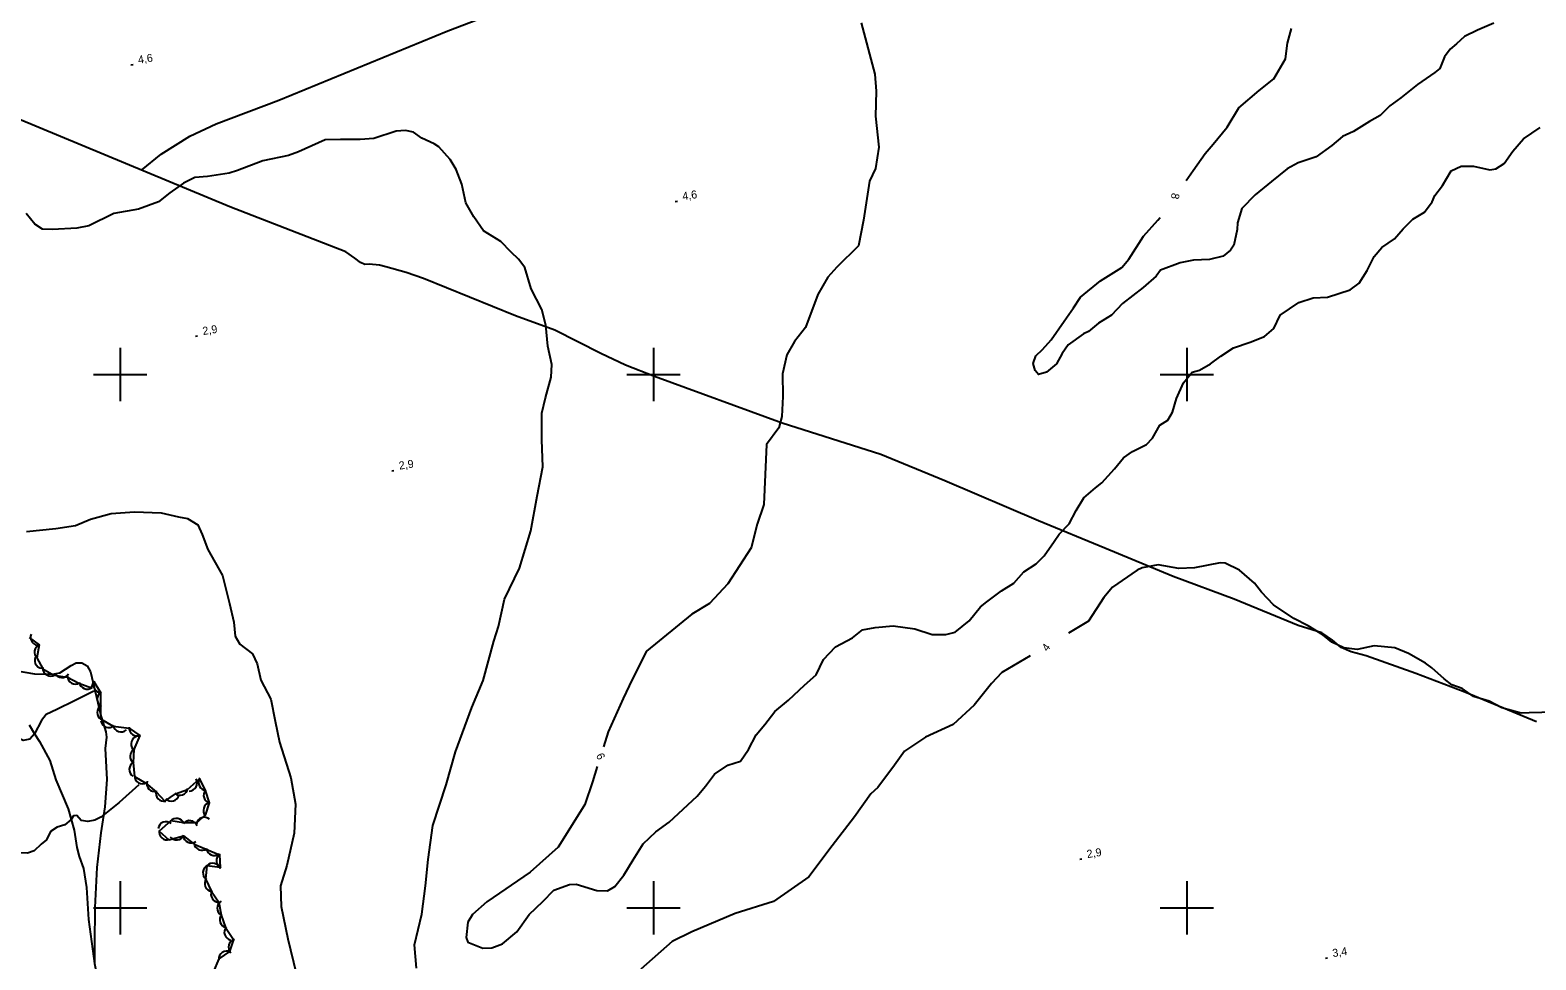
# Model space of a CAD drawing. Extents: x 643342 to 646936, y 5873857 to 5876103.
# Drawn here: x 644566 to 645131, y 5874980 to 5875329 of the extents above; entities that cross this region are included whole.
import ezdxf

# ---------------------------------------------------------------- set-up
doc = ezdxf.new("R2010")
doc.units = 0
for name, color, linetype in [('Niveau 2', 7, 'Continuous'), ('Niveau 22', 7, 'Continuous'), ('Niveau 3', 7, 'Continuous'), ('Niveau 4', 7, 'Continuous'), ('Niveau 44', 7, 'Continuous'), ('Niveau 61', 7, 'Continuous')]:
    doc.layers.add(name, color=color, linetype=linetype)

msp = doc.modelspace()

# ---------------------------------------------------------------- linework, layer by layer
at = {"layer": 'Niveau 2'}
for points in [[(644877.82, 5875331.83), (644882.97, 5875312.58), (644883.46, 5875306.17), (644883.2, 5875296.74), (644884.42, 5875285.11), (644883.2, 5875277.12), (644880.91, 5875272.44), (644878.75, 5875257.84), (644876.88, 5875248.14), (644868.67, 5875240.18), (644865.31, 5875236.39), (644861.62, 5875229.87), (644856.91, 5875217.54), (644852.86, 5875212.33), (644849.95, 5875207.34), (644848.3, 5875200.24), (644848.53, 5875191.67), (644848.07, 5875184.22), (644846.96, 5875179.99), (644842.31, 5875173.66), (644841.3, 5875151.19), (644838.84, 5875143.89), (644836.54, 5875134.95), (644827.79, 5875121.51), (644820.97, 5875114.07), (644814.35, 5875110.07), (644797.34, 5875096.17), (644791.92, 5875085.62), (644788.62, 5875078.46), (644783.03, 5875066), (644781.23, 5875060.3)], [(645115.06, 5875331.59), (645108.98, 5875328.98), (645104.09, 5875326.65), (645100.99, 5875323.96), (645098.66, 5875321.87), (645096.51, 5875319.03), (645094.79, 5875314.65), (645092.88, 5875313.12), (645086.48, 5875308.72), (645080.13, 5875303.67), (645076, 5875300.71), (645072.46, 5875297.04), (645068.44, 5875294.73), (645062.38, 5875291), (645058.33, 5875289.16), (645054.35, 5875285.74), (645048.45, 5875281.55), (645041.73, 5875279.23), (645037.53, 5875277.03), (645031.73, 5875272.32), (645025.54, 5875267.34), (645020.54, 5875262.12), (645018.9, 5875256.85), (645018.77, 5875254.31), (645017.58, 5875248.43), (645016.29, 5875246.49), (645013.6, 5875244.36), (645008.43, 5875243.06)], [(644999.69, 5875272.64), (645002.26, 5875276.43), (645006.81, 5875282.73), (645009.79, 5875286.24), (645015.09, 5875292.67), (645019.38, 5875299.88), (645027.07, 5875306.46), (645032.56, 5875310.73), (645036.88, 5875318.23), (645037.71, 5875324.13), (645039.22, 5875329.67)], [(644731.83, 5875075.08), (644736.15, 5875085.19), (644740.14, 5875099.99), (644741.84, 5875105.47), (644744.15, 5875115.74), (644749.73, 5875127.38), (644754.02, 5875141.37), (644756.31, 5875154.34), (644758.43, 5875165.29), (644758.17, 5875175.47), (644758.17, 5875185.44), (644759.43, 5875191.22), (644761.62, 5875198.98), (644761.88, 5875203.67), (644760.41, 5875210.55), (644759.67, 5875218.44), (644758.11, 5875224.37), (644754.12, 5875232), (644751.78, 5875240.04), (644749.38, 5875243.17), (644746.62, 5875245.74), (644742.78, 5875249.86), (644736.22, 5875253.77), (644732.56, 5875259.09), (644729.66, 5875264.35), (644728.12, 5875271.34), (644725.97, 5875276.8), (644723.75, 5875280.48), (644719.44, 5875285.32), (644717.75, 5875286.46), (644713.11, 5875288.5), (644709.96, 5875290.85), (644706.98, 5875291.46), (644703.5, 5875291.13), (644695.15, 5875288.45), (644690.03, 5875288.09), (644682.61, 5875288.03), (644676.93, 5875287.97), (644666.82, 5875283.36), (644663.08, 5875282.06), (644653.49, 5875279.98), (644643.99, 5875276.36), (644640.86, 5875275.36), (644632.71, 5875274.12), (644628.05, 5875273.85), (644623.79, 5875271.68), (644618.63, 5875268), (644614.37, 5875264.65), (644606.94, 5875261.88), (644597.65, 5875260.29), (644588.28, 5875255.68), (644583.72, 5875254.78), (644574.61, 5875254.27), (644570.96, 5875254.4), (644568.03, 5875256.25), (644564.83, 5875260.26)], [(645091.95, 5875264.62), (645092.91, 5875267), (645095.75, 5875270.74), (645099.01, 5875276.33), (645102.78, 5875278.09), (645107.41, 5875278.1), (645113.51, 5875276.72), (645115.83, 5875277.05), (645118.88, 5875278.98), (645122.16, 5875283.64), (645126.21, 5875288.24), (645132.44, 5875292.58)], [(644968.08, 5875159.29), (644972.86, 5875164.57), (644976.25, 5875168.66), (644979.57, 5875171.04), (644984.77, 5875173.65), (644987.04, 5875176.1), (644989.77, 5875180.95), (644992.84, 5875182.87), (644994.58, 5875185.81), (644996.01, 5875190.95), (644998.67, 5875196.8), (645001.96, 5875200.82), (645004.66, 5875201.6), (645008.86, 5875203.94), (645012.67, 5875206.82), (645017.5, 5875209.98), (645023.67, 5875212.09), (645029.06, 5875214.24), (645032.56, 5875217.15), (645034.89, 5875222.14), (645041.98, 5875226.98), (645047.29, 5875228.71), (645052.73, 5875228.92), (645061.12, 5875231.64), (645064.54, 5875234.19), (645067.53, 5875238.88), (645070.17, 5875244.19), (645073.04, 5875247.57), (645077.75, 5875250.78), (645081, 5875254.49), (645084.67, 5875258.12), (645089.07, 5875260.77), (645091.95, 5875264.62)], [(645008.43, 5875243.06), (645002.47, 5875242.8), (644997.44, 5875241.81), (644990.11, 5875239.01), (644988.48, 5875236.86), (644983.52, 5875232.52), (644975.77, 5875226.51), (644971.74, 5875222.19), (644966.78, 5875219.14), (644963.05, 5875216.09), (644961.25, 5875215.15), (644955.49, 5875211.09), (644953.25, 5875207.82), (644951.12, 5875203.97), (644947.34, 5875200.85), (644944.3, 5875199.98), (644943.05, 5875201.39), (644942.35, 5875204.04), (644943.33, 5875206.96), (644945.83, 5875209.31), (644949.03, 5875212.96), (644953.89, 5875219.95), (644957.51, 5875224.88), (644960.03, 5875228.94), (644967.61, 5875235.05), (644975.52, 5875240.02), (644978.17, 5875243.21), (644983.64, 5875251.84), (644989.11, 5875257.75), (644990, 5875258.82)], [(644778.9, 5875052.94), (644777.09, 5875047.2), (644774.27, 5875038.78), (644767.56, 5875028.1), (644764.21, 5875022.81), (644753.75, 5875013.41), (644737.55, 5875002.26), (644732.15, 5874997.53), (644730.32, 5874994.58), (644729.69, 5874988.91), (644730.38, 5874987.14), (644735.97, 5874984.92), (644739.41, 5874985.02), (644743.42, 5874986.54), (644748.79, 5874991.02), (644753.38, 5874997.55), (644758.54, 5875002.37), (644762.64, 5875006.61), (644768.52, 5875008.72), (644770.96, 5875008.84), (644778.72, 5875006.47), (644782.7, 5875006.39), (644785.47, 5875008.02), (644788.86, 5875012.31), (644792.3, 5875018.01), (644796.05, 5875023.98), (644800.83, 5875028.46), (644805.91, 5875032.09), (644816.31, 5875041.83), (644819.46, 5875045.62), (644822.88, 5875050.14), (644827.88, 5875053.45), (644832.63, 5875055.04), (644835.66, 5875059.34), (644838.46, 5875064.86), (644841.71, 5875068.77), (644845.5, 5875073.62), (644850.59, 5875077.83), (644856.58, 5875083.48), (644860.99, 5875087.32), (644863.76, 5875093.13), (644868.27, 5875097.86), (644874.53, 5875101.24), (644878.38, 5875104.26), (644883.08, 5875105.07), (644889.83, 5875105.73), (644897.92, 5875104.57), (644904.52, 5875102.44), (644909.58, 5875102.52), (644913.05, 5875103.33), (644918.36, 5875107.55), (644922.63, 5875112.79), (644925, 5875114.78), (644930.49, 5875118.79), (644935.04, 5875121.76), (644938.88, 5875126.01), (644943.43, 5875128.92), (644946.51, 5875131.93), (644950.24, 5875137.35), (644952.07, 5875140.11), (644955.83, 5875143.94), (644958.43, 5875149.01), (644961.35, 5875153.76), (644965.65, 5875157.41), (644968.08, 5875159.29)], [(644564.93, 5875141.14), (644575.89, 5875142.19), (644583.32, 5875143.32), (644588.92, 5875145.7), (644596.67, 5875147.8), (644605.36, 5875148.52), (644615.45, 5875148.13), (644621.95, 5875146.56), (644625.3, 5875145.94), (644629.1, 5875143.58), (644630.79, 5875140.01), (644632.85, 5875134.35), (644638.35, 5875124.63), (644641.04, 5875114.06), (644642.64, 5875107.1), (644643.19, 5875101.89), (644644.94, 5875098.8), (644649.63, 5875095.22), (644651.4, 5875091.43), (644652.73, 5875085.34), (644656.52, 5875078.18), (644658.17, 5875069.99), (644659.79, 5875062.09), (644663.98, 5875048.75), (644665.74, 5875038.85), (644665.23, 5875028.02), (644662.49, 5875015.9), (644660.15, 5875008.2), (644660.35, 5875000.45), (644662.9, 5874988.37), (644665.99, 5874975.51)], [(645137.73, 5875073.38), (645128.24, 5875073.06), (645125.31, 5875073.02), (645118.02, 5875074.99), (645113.34, 5875077.43), (645107.42, 5875079.23), (645103.22, 5875082.2), (645099.27, 5875083.65), (645096.44, 5875085.8), (645091.83, 5875090.03), (645089.39, 5875091.75), (645083.07, 5875095.4), (645077.95, 5875097.45), (645074.09, 5875097.8), (645070.18, 5875098.19), (645063.76, 5875096.88), (645058.77, 5875097.47), (645054.28, 5875099.59), (645050.99, 5875102.29), (645045.45, 5875105.66), (645040.08, 5875108.46), (645032.44, 5875113.59), (645027.96, 5875118.3), (645025.31, 5875121.71), (645019.69, 5875126.62), (645014.34, 5875129.19), (645012.39, 5875129.3), (645002.77, 5875127.45), (644996.9, 5875127.2), (644989.18, 5875128.54), (644983.2, 5875127.44), (644981.33, 5875126.56), (644972.1, 5875120.26), (644968.85, 5875116.29), (644963.13, 5875107.53), (644955.6, 5875103.02)], [(644941.18, 5875094.51), (644930.59, 5875088.21), (644926.7, 5875084.05), (644920.21, 5875075.99), (644912.34, 5875068.73), (644902, 5875063.97), (644894.11, 5875058.76), (644890.29, 5875053.55), (644884.03, 5875045.1), (644881.51, 5875042.78)], [(644711.15, 5874977.38), (644710.32, 5874986.18), (644713.12, 5874997.57), (644714.46, 5875008.24), (644715.52, 5875018.16), (644717.25, 5875030.86), (644722.26, 5875046.13), (644725.77, 5875058.54), (644731.83, 5875075.08)], [(644881.51, 5875042.78), (644875.32, 5875034.15), (644867.01, 5875023.3), (644858.2, 5875011.58), (644844.93, 5875002.36), (644830.63, 5874997.88), (644814.33, 5874990.96), (644806.95, 5874987.4), (644795.17, 5874977.02)]]:
    msp.add_lwpolyline(points, dxfattribs=at)
at = {"layer": 'Niveau 22'}
for points in [[(644607.99, 5875276.54), (644615.34, 5875282.58), (644626.17, 5875289.28), (644635.97, 5875293.95), (644659.53, 5875302.81), (644722.84, 5875328.77), (644742.2, 5875336.13), (644757.56, 5875339.67), (644787.87, 5875347.1), (644846.76, 5875359.49), (644883.37, 5875366.24), (644949.1, 5875380.73), (645027.75, 5875398.1), (645075.65, 5875409.44), (645188.89, 5875433.56), (645246.8, 5875436.74), (645254.39, 5875435.12), (645258.48, 5875433.17), (645290.98, 5875420.13), (645338.2, 5875400.85), (645403.78, 5875377.34), (645494.14, 5875342.72), (645576.71, 5875308.93), (645614.3, 5875294.03)], [(645131.03, 5875069.79), (645104.11, 5875080.89), (645085.84, 5875087.81), (645067.2, 5875094.5), (645061.6, 5875095.99), (645057.86, 5875097.55), (645054.59, 5875100.41), (645050.56, 5875103.11), (645041.63, 5875105.8), (645017.64, 5875115.77), (644994.85, 5875124.26), (644969.18, 5875134.86), (644944.34, 5875145.04), (644909.18, 5875160.07), (644885.18, 5875169.91), (644848.27, 5875181.69), (644800.37, 5875199.17), (644789.48, 5875203.41), (644780.24, 5875207.77), (644763.03, 5875216.5), (644748.23, 5875221.9), (644713.73, 5875235.89), (644707.24, 5875238.22), (644699.59, 5875240.32), (644697.19, 5875240.91), (644693.4, 5875241.26), (644691.74, 5875241.22), (644690.08, 5875241.88), (644688.04, 5875243.53), (644684.58, 5875245.95), (644641.12, 5875262.8), (644538.46, 5875305.37)], [(644553.98, 5875090.12), (644567.9, 5875087.72), (644574.68, 5875087.55), (644577.39, 5875088.14), (644581.6, 5875090.81), (644583.49, 5875091.83), (644585.64, 5875091.89), (644587.59, 5875090.77), (644588.95, 5875088.42), (644589.95, 5875084.18), (644592.87, 5875071.55), (644594.66, 5875066), (644594.91, 5875063.95), (644594.45, 5875059.7), (644595.02, 5875048.17), (644594.33, 5875037.82), (644592.8, 5875028.1), (644591.32, 5875015.13), (644590.58, 5875000.17), (644590.44, 5874986.42), (644590.41, 5874979.26)], [(644565.94, 5875068.56), (644567.86, 5875065.24), (644569.78, 5875062.34), (644573.63, 5875055.23), (644575.96, 5875047.98), (644580.53, 5875037.16), (644581.6, 5875033.13), (644582.8, 5875029.09), (644583.76, 5875022.65), (644584.66, 5875019.3), (644586.27, 5875014.7), (644587.41, 5875007.57), (644588.17, 5874995.64), (644590.43, 5874979.11), (644592.72, 5874967.22), (644597.04, 5874955.05), (644600.41, 5874943.02), (644604.2, 5874932.7), (644608.59, 5874924.82), (644611.15, 5874921.39), (644615.82, 5874914.37), (644618.02, 5874912.21), (644620.68, 5874909.03), (644623.57, 5874904.56)]]:
    msp.add_lwpolyline(points, dxfattribs=at)
at = {"layer": 'Niveau 3'}
for p, q in [((644604.07, 5875316.01), (644604.87, 5875316.14)), ((644808.16, 5875264.82), (644808.95, 5875264.94)), ((644628.28, 5875214.31), (644629.07, 5875214.44)), ((644701.89, 5875163.84), (644702.68, 5875163.97)), ((644959.8, 5875018.23), (644960.59, 5875018.36)), ((645051.9, 5874981.1), (645052.69, 5874981.22))]:
    msp.add_line(p, q, dxfattribs=at)
at = {"layer": 'Niveau 4'}
for points in [[(644590.18, 5875081.17), (644582.86, 5875077.62), (644576.32, 5875074.37), (644572.26, 5875072.43), (644570.58, 5875070.25), (644567.86, 5875065.24), (644566.16, 5875063.29), (644563.62, 5875062.69), (644561.77, 5875063.58), (644559.21, 5875063.21), (644556.8, 5875061.2), (644551.2, 5875056.73), (644544, 5875047.95), (644542.58, 5875044.13), (644540.54, 5875042.03), (644536.81, 5875041.43), (644533.47, 5875042.93)], [(644607.01, 5875046.17), (644599.62, 5875039.51), (644592.72, 5875033.97), (644590.47, 5875032.81), (644587.92, 5875032.32), (644585.4, 5875032.79), (644583.82, 5875034.65), (644582.53, 5875034.52), (644581.6, 5875033.13), (644579.31, 5875031.12), (644576.45, 5875030.25), (644573.89, 5875028.58), (644572.41, 5875025.46), (644570.44, 5875023.84), (644567.73, 5875021.32), (644565.33, 5875020.49), (644560.83, 5875020.65), (644551.94, 5875023.58), (644546.54, 5875024.22)]]:
    msp.add_lwpolyline(points, dxfattribs=at)
at = {"layer": 'Niveau 44'}
for points in [[(644565.9, 5875101.29), (644569.6, 5875098.54), (644568.72, 5875093.76), (644570.99, 5875089.57), (644575.21, 5875087.17), (644580.26, 5875086.53), (644584.51, 5875084.18), (644589.24, 5875082.45), (644590.11, 5875084.81), (644592.64, 5875080.68), (644592.64, 5875075.83), (644592.63, 5875070.83), (644597.38, 5875068.14), (644603.41, 5875067.41), (644607.35, 5875064.57), (644605.14, 5875059.37), (644604.85, 5875054.53), (644605.44, 5875049.23), (644609.61, 5875046.74)], [(644609.61, 5875046.74), (644613.46, 5875043.51), (644616.81, 5875039.99), (644620.74, 5875042.75), (644625.3, 5875044.41), (644629.73, 5875048.38), (644631.89, 5875043.93), (644633.37, 5875039.31), (644631.83, 5875034.69), (644628.7, 5875031.83), (644623.82, 5875031.87), (644619.04, 5875032.68), (644614.61, 5875028.73), (644618.26, 5875025.53), (644623.72, 5875027), (644627.79, 5875023.89), (644632.26, 5875021.99), (644637.2, 5875019.93), (644637.5, 5875015.09), (644632.47, 5875015.74), (644632.07, 5875010.9), (644634.21, 5875006.07), (644637, 5875002.1), (644637.87, 5874997.26), (644639.52, 5874992.69), (644642.56, 5874988.1), (644641, 5874983.66), (644637.02, 5874980.88), (644634.94, 5874975.88)]]:
    msp.add_lwpolyline(points, dxfattribs=at)
for centre, start, end in [((644569.4, 5875101.42), 157.2526, 277.2306), ((644569.4, 5875101.42), 157.2526, 277.2306), ((644569.4, 5875101.42), 157.2526, 277.2306), ((644570.89, 5875095.83), 109.5321, 229.5101), ((644570.89, 5875095.83), 109.5321, 229.5101), ((644570.89, 5875095.83), 109.5321, 229.5101), ((644570.95, 5875092.82), 158.4, 278.3779), ((644570.95, 5875092.82), 158.4, 278.3779), ((644570.95, 5875092.82), 158.4, 278.3779), ((644573.97, 5875089.9), 180.3185, 300.2964), ((644573.97, 5875089.9), 180.3185, 300.2964), ((644573.97, 5875089.9), 180.3185, 300.2964), ((644578.19, 5875089.34), 206.2741, 326.252), ((644578.19, 5875089.34), 206.2741, 326.252), ((644578.19, 5875089.34), 206.2741, 326.252), ((644583.24, 5875086.9), 181.0271, 301.005), ((644583.24, 5875086.9), 181.0271, 301.005), ((644583.24, 5875086.9), 181.0271, 301.005), ((644587.62, 5875084.97), 188.7955, 308.7734), ((644587.62, 5875084.97), 188.7955, 308.7734), ((644587.62, 5875084.97), 188.7955, 308.7734), ((644592.89, 5875083.68), 151.8148, 271.7928), ((644592.89, 5875083.68), 151.8148, 271.7928), ((644592.89, 5875083.68), 151.8148, 271.7928), ((644594.4, 5875078.25), 119.9334, 239.9114), ((644594.4, 5875078.25), 119.9334, 239.9114), ((644594.4, 5875078.25), 119.9334, 239.9114), ((644594.39, 5875073.25), 119.9334, 239.9114), ((644594.39, 5875073.25), 119.9334, 239.9114), ((644594.39, 5875073.25), 119.9334, 239.9114), ((644595.67, 5875070.61), 190.7566, 310.7345), ((644595.67, 5875070.61), 190.7566, 310.7345), ((644595.67, 5875070.61), 190.7566, 310.7345), ((644600.39, 5875068.96), 190.7566, 310.7345), ((644600.39, 5875068.96), 190.7566, 310.7345), ((644600.39, 5875068.96), 190.7566, 310.7345), ((644606.41, 5875067.42), 174.1893, 294.1673), ((644606.41, 5875067.42), 174.1893, 294.1673), ((644606.41, 5875067.42), 174.1893, 294.1673), ((644606.75, 5875056.84), 116.5386, 236.5165), ((644606.75, 5875056.84), 116.5386, 236.5165), ((644606.75, 5875056.84), 116.5386, 236.5165), ((644607.09, 5875061.42), 101.1168, 221.0948), ((644607.09, 5875061.42), 101.1168, 221.0948), ((644607.09, 5875061.42), 101.1168, 221.0948), ((644606.45, 5875051.85), 116.5386, 236.5165), ((644606.45, 5875051.85), 116.5386, 236.5165), ((644606.45, 5875051.85), 116.5386, 236.5165), ((644608.43, 5875049.5), 179.2138, 299.1917), ((644608.43, 5875049.5), 179.2138, 299.1917), ((644608.43, 5875049.5), 179.2138, 299.1917), ((644625.89, 5875046.8), 270.4303, 30.4082), ((644625.89, 5875046.8), 270.4303, 30.4082), ((644625.89, 5875046.8), 270.4303, 30.4082), ((644632.4, 5875047.02), 147.0612, 267.0391), ((644632.4, 5875047.02), 147.0612, 267.0391), ((644632.4, 5875047.02), 147.0612, 267.0391), ((644612.97, 5875046.59), 163.5422, 283.5201), ((644612.97, 5875046.59), 163.5422, 283.5201), ((644612.97, 5875046.59), 163.5422, 283.5201), ((644616.41, 5875042.97), 163.5422, 283.5201), ((644616.41, 5875042.97), 163.5422, 283.5201), ((644616.41, 5875042.97), 163.5422, 283.5201), ((644622.42, 5875045.24), 230.0958, 350.0737), ((644622.42, 5875045.24), 230.0958, 350.0737), ((644622.42, 5875045.24), 230.0958, 350.0737), ((644634.31, 5875042.16), 137.8275, 257.8054), ((644634.31, 5875042.16), 137.8275, 257.8054), ((644634.31, 5875042.16), 137.8275, 257.8054), ((644619.25, 5875043.03), 223.773, 343.7509), ((644619.25, 5875043.03), 223.773, 343.7509), ((644619.25, 5875043.03), 223.773, 343.7509), ((644634.23, 5875036.48), 102.7351, 222.713), ((644634.23, 5875036.48), 102.7351, 222.713), ((644634.23, 5875036.48), 102.7351, 222.713), ((644617.21, 5875029.28), 50.9419, 170.9198), ((644617.21, 5875029.28), 50.9419, 170.9198), ((644617.21, 5875029.28), 50.9419, 170.9198), ((644621.14, 5875030.53), 20.4772, 140.4552), ((644621.14, 5875030.53), 20.4772, 140.4552), ((644621.14, 5875030.53), 20.4772, 140.4552), ((644626.07, 5875029.71), 20.4772, 140.4552), ((644626.07, 5875029.71), 20.4772, 140.4552), ((644626.07, 5875029.71), 20.4772, 140.4552), ((644631.57, 5875030.97), 49.3533, 169.3313), ((644631.57, 5875030.97), 49.3533, 169.3313), ((644631.57, 5875030.97), 49.3533, 169.3313), ((644617.6, 5875028.46), 168.8716, 288.8496), ((644617.6, 5875028.46), 168.8716, 288.8496), ((644617.6, 5875028.46), 168.8716, 288.8496), ((644621.11, 5875028.46), 216.7512, 336.7291), ((644621.11, 5875028.46), 216.7512, 336.7291), ((644621.11, 5875028.46), 216.7512, 336.7291), ((644626.63, 5875027.35), 185.2099, 305.1878), ((644626.63, 5875027.35), 185.2099, 305.1878), ((644626.63, 5875027.35), 185.2099, 305.1878), ((644630.71, 5875024.56), 187.0151, 306.993), ((644630.71, 5875024.56), 187.0151, 306.993), ((644630.71, 5875024.56), 187.0151, 306.993), ((644635.31, 5875022.61), 187.0151, 306.993), ((644635.31, 5875022.61), 187.0151, 306.993), ((644635.31, 5875022.61), 187.0151, 306.993), ((644639.11, 5875017.62), 123.5801, 243.5581), ((644639.11, 5875017.62), 123.5801, 243.5581), ((644639.11, 5875017.62), 123.5801, 243.5581), ((644634.03, 5875013.18), 115.2564, 235.2344), ((644634.03, 5875013.18), 115.2564, 235.2344), ((644634.03, 5875013.18), 115.2564, 235.2344), ((644634.79, 5875013.73), 19.1806, 139.1586), ((644634.79, 5875013.73), 19.1806, 139.1586), ((644634.79, 5875013.73), 19.1806, 139.1586), ((644634.7, 5875009.1), 141.8215, 261.7994), ((644634.7, 5875009.1), 141.8215, 261.7994), ((644634.7, 5875009.1), 141.8215, 261.7994), ((644637.05, 5875005.1), 155.1835, 275.1614), ((644637.05, 5875005.1), 155.1835, 275.1614), ((644637.05, 5875005.1), 155.1835, 275.1614), ((644639.36, 5874999.89), 120.6344, 240.6123), ((644639.36, 5874999.89), 120.6344, 240.6123), ((644639.36, 5874999.89), 120.6344, 240.6123), ((644640.35, 5874995.57), 139.8734, 259.8513), ((644640.35, 5874995.57), 139.8734, 259.8513), ((644640.35, 5874995.57), 139.8734, 259.8513), ((644642.05, 5874990.87), 139.8734, 259.8513), ((644642.05, 5874990.87), 139.8734, 259.8513), ((644642.05, 5874990.87), 139.8734, 259.8513), ((644643.62, 5874985.29), 104.6524, 224.6304), ((644643.62, 5874985.29), 104.6524, 224.6304), ((644643.62, 5874985.29), 104.6524, 224.6304), ((644640.02, 5874980.83), 64.9898, 184.9678), ((644640.02, 5874980.83), 64.9898, 184.9678), ((644640.02, 5874980.83), 64.9898, 184.9678)]:
    msp.add_arc(centre, 3, start, end, dxfattribs=at)
at = {"layer": 'Niveau 61'}
for points in [[(644600, 5875210), (644600, 5875200), (644600, 5875190)], [(644800, 5875210), (644800, 5875200), (644800, 5875190)], [(645000, 5875210), (645000, 5875200), (645000, 5875190)], [(644590, 5875200), (644600, 5875200), (644610, 5875200)], [(644790, 5875200), (644800, 5875200), (644810, 5875200)], [(644990, 5875200), (645000, 5875200), (645010, 5875200)], [(644600, 5875010), (644600, 5875000), (644600, 5874990)], [(644800, 5875010), (644800, 5875000), (644800, 5874990)], [(645000, 5875010), (645000, 5875000), (645000, 5874990)], [(644590, 5875000), (644600, 5875000), (644610, 5875000)], [(644790, 5875000), (644800, 5875000), (644810, 5875000)], [(644990, 5875000), (645000, 5875000), (645010, 5875000)]]:
    msp.add_lwpolyline(points, dxfattribs=at)

# ---------------------------------------------------------------- texts
at = {"layer": 'Niveau 2'}
for s, rotation, p in [('8', 259.5331, (644994.33, 5875268.16)), ('4', 53.2892, (644947.66, 5875095.9)), ('6', 295.1541, (644778.34, 5875057.18))]:
    msp.add_text(s, height=3, rotation=rotation, dxfattribs=at).set_placement(p)
at = {"layer": 'Niveau 3'}
for s, rotation, p in [('4,6  ', 8.941, (644606.93, 5875316.42)), ('4,6  ', 8.941, (644811.01, 5875265.23)), ('2,9  ', 8.941, (644631.13, 5875214.72)), ('2,9  ', 8.941, (644704.74, 5875164.25)), ('2,9  ', 8.9405, (644962.65, 5875018.64)), ('3,4  ', 8.9405, (645054.75, 5874981.51))]:
    msp.add_text(s, height=3, rotation=rotation, dxfattribs=at).set_placement(p)

doc.saveas('drawing.dxf')
